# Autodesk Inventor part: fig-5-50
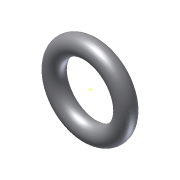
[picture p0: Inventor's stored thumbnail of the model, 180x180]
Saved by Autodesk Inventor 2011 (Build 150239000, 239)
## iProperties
Created: 2010-02
Part Number: fig-5-50
Document SubType Name: Modeling
Designer: CADSoft
Density: 1 g/cm^3
Author: CADSoft
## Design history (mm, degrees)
sketch "Sketch1"
  geometry: L1 (0, 21.37)-(0, -16.247); C1 r 5 at (20.026, 0); 1 further point
  constraints: 2 end point, 1 centre point
  dimensions: "d0" = 10 diameter of C1
revolve "Revolution1" sketch "Sketch1" stored, may be unused: angle "d1" = 90 deg
workpoint "Work Point1"
body "Solid1"
